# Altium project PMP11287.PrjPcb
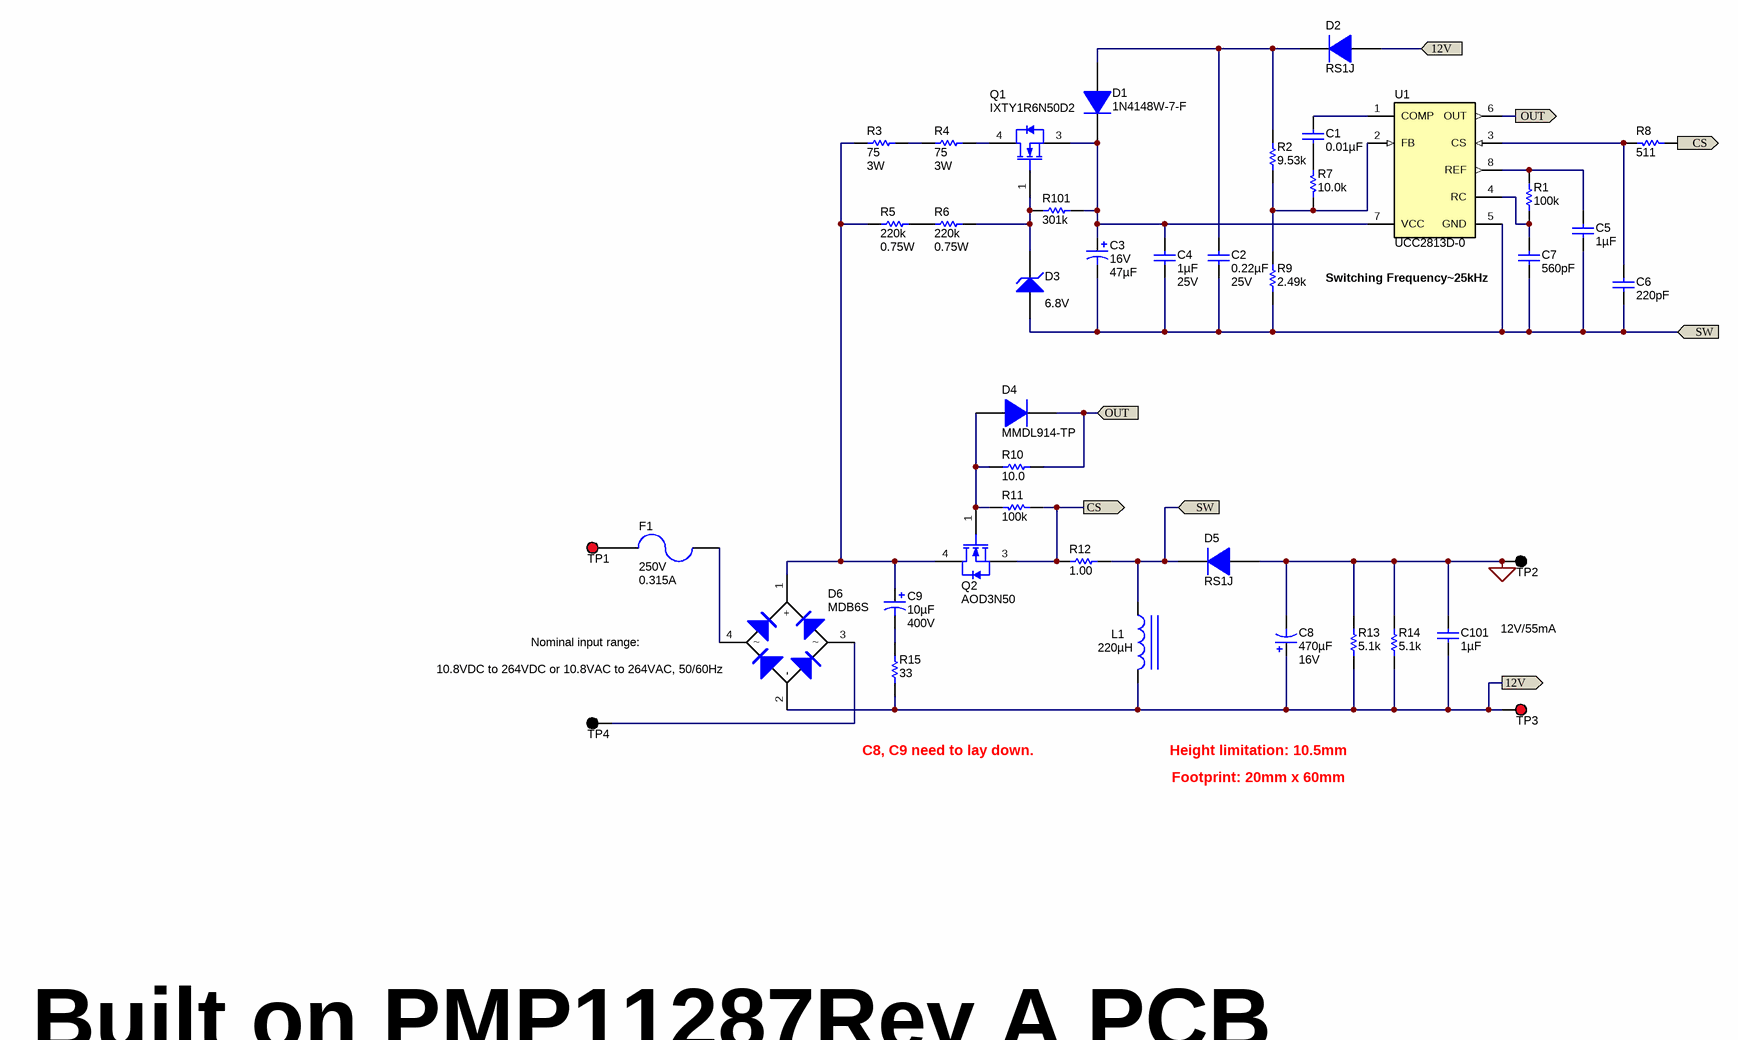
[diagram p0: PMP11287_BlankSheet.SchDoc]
TechSupport: http://www.ti.com/support; SCH_Rev: A; PRJ_Title: Ultra wide input range Buck-Boost converter; PRJ_Number: PMP20182; PRJ_Engineer: Sheng-Yang Yu; PRJ_Customer: Public Release; PCB_Rev: A; PCB_Layout: Sheng-Yang Yu; EVM_Orderable: N/A; CopyrightYear: 2016
1 sheet, 41 parts. Net scope: flat (ports and power ports of the same name join across sheets).
Board file: PMP11287_TID.PcbDoc

## Sheet PMP11287_BlankSheet.SchDoc
size 431 x 279 mm; Date: Not shown in title block; ApprovedBy: Not shown in title block; CheckedBy: Not shown in title block; Author: Not shown in title block; CompanyName: Not shown in title block; Engineer: Not shown in title block; Organization: Not shown in title block; Address1: Not shown in title block; Address2: Not shown in title block; Address3: Not shown in title block; Address4: Not shown in title block; DocumentNumber: 1; Revision: Use project parameter SCH_Rev; SheetNumber: 1; SheetTotal: 1; PageSetup: Record=PageOptions¦CenterHorizontal=True¦CenterVertical=True¦PrintScale=1.00¦XCorrection=1.00¦YCorrection=1.00¦PrintKind=0¦BorderSize=5000000¦LeftOffset=0¦BottomOffset=0¦Orientation=2¦PaperLength=1000¦PaperWidth=1000¦Scale=100¦PaperSource=15¦PrintQuality=600¦MediaType=1¦DitherType=10¦PaperKind=Letter¦PrintScaleMode=1

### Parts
C1  ValueDisplayed: 0.01µF  [0603]  (hidden comment: 06031C103MAT2A)
C2  ValueDisplayed: 0.22µF  Value2: 25V  [0603]  (hidden comment: 06033D224KAT2A)
C3  Value2: 16V  ValueDisplayed: 47µF  [SEPC_C9]  (hidden comment: UVR1C470MDD1TD)
C4  ValueDisplayed: 1µF  Value2: 25V  [1206]  (hidden comment: 12063C105KAT2A)
C5  ValueDisplayed: 1µF  [1206]  (hidden comment: GCM31MR71E105KA37L)
C6  ValueDisplayed: 220pF  [0603]  (hidden comment: GRM1885C1H221JA01D)
C7  ValueDisplayed: 560pF  [0603]  (hidden comment: 06035A561JAT2A)
C8  ValueDisplayed: 470µF  Value2: 16V  [ZL_1000x1600]  (hidden comment: 16YXG470MEFC10X12.5)
C9  ValueDisplayed: 10µF  Value2: 400V  [PW_1000x2000]  (hidden comment: UCS2G100MPD)
C101  ValueDisplayed: 1µF  [0805_HV]  (hidden comment: GRM216R61E105KA12D)
D1  1N4148W-7-F  [SOD-123]
D2  RS1J  [SMA]
D3  value 6.8V  [SOD-123]  (hidden comment: MMSZ5235B-7-F)
D4  MMDL914-TP  [sod-323]
D5  RS1J  [SMA]
D6  MDB6S  [MICRODIP_4]
F1  VAC_V: 250V  Irating_A: 0.315A  [FUSE_372]  (hidden comment: 37203150001)
L1  ValueDisplayed: 220µH  [SDR1006]  (hidden comment: SDR1006-221KL)
Q1  IXTY1R6N50D2  [DPAK]
Q2  AOD3N50  [DPAK]
R1  ValueDisplayed: 100k  [0603]  (hidden comment: CRCW0603100KFKEA)
R2  ValueDisplayed: 9.53k  [0603]  (hidden comment: CRCW06039K53FKEA)
R3  ValueDisplayed: 75  Value2: 3W  [RESAD2032W80L1300D480]  (hidden comment: PNP300JR-73-75R)
R4  ValueDisplayed: 75  Value2: 3W  [RESAD2032W80L1300D480]  (hidden comment: PNP300JR-73-75R)
R5  ValueDisplayed: 220k  Value2: 0.75W  [2010]  (hidden comment: CRCW2010220KJNEF)
R6  ValueDisplayed: 220k  Value2: 0.75W  [2010]  (hidden comment: CRCW2010220KJNEF)
R7  value 10.0k  [0603]  (hidden comment: CRCW060310K0FKEA)
R8  value 511  [0603]  (hidden comment: CRCW0603511RFKEA)
R9  value 2.49k  [0603]  (hidden comment: CRCW06032K49FKEA)
R10  ValueDisplayed: 10.0  [0603]  (hidden comment: CRCW060310R0FKEA)
R11  value 100k  [0603]  (hidden comment: CRCW0603100KFKEA)
R12  ValueDisplayed: 1.00  [1206]  (hidden comment: CRCW12061R00FKEA)
R13  ValueDisplayed: 5.1k  [1206]  (hidden comment: CRCW12065K10JNEA)
R14  ValueDisplayed: 5.1k  [1206]  (hidden comment: CRCW12065K10JNEA)
R15  ValueDisplayed: 33  [2512]  (hidden comment: CRM2512-FX-33R0ELF)
R101  ValueDisplayed: 301k  [1206]  (hidden comment: ERJ-8ENF3013V)
TP1  5000  [Keystone5000]  (value not drawn)
TP2  5001  [Keystone5001]  (value not drawn)
TP3  5000  [Keystone5000]  (value not drawn)
TP4  5001  [Keystone5001]  (value not drawn)
U1  UCC2813D-0  [D0008A_N]

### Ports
12V (in), 12V (out), CS (in), CS (out), OUT (in), OUT (out), SW (in)

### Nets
GND: C8.2(-) C101.1 D5.2(A) R13.2 R14.2 TP2.1
12V: C8.1(+) C101.2 D2.2(A) D6.2(-) L1.2 R13.1 R14.1 R15.1 TP3.1 ; port 12V
CS: Q2.3(S) R8.1 R11.2 R12.1 ; port CS
OUT: D4.1(K) R10.2 U1.6(OUT) ; port OUT
SW: C2.2 C3.2(-) C4.2 C5.2 C6.2 C7.2 D3.2(A) D5.1(K) L1.1 R9.1 R12.2 U1.5(GND) ; port SW
NetC1_1: C1.1 U1.1(COMP)
NetC1_2: C1.2 R7.1
NetC2_1: C2.1 D1.2(A) D2.1(K) R2.2
NetC3_1: C3.1(+) C4.1 D1.1(K) Q1.3(S) R101.2 U1.7(VCC)
NetC5_1: C5.1 R1.2 U1.8(REF)
NetC6_1: C6.1 R8.2 U1.3(CS)
NetC7_1: C7.1 R1.1 U1.4(RC)
NetC9_1: C9.1(+) D6.1(+) Q2.4(D) R3.1 R5.2
NetC9_2: C9.2(-) R15.2
NetD3_1: D3.1(K) Q1.1(G) R6.1 R101.1
NetD4_2: D4.2(A) Q2.1(G) R10.1 R11.1
NetD6_3: D6.3 TP4.1
NetD6_4: D6.4 F1.1
NetF1_2: F1.2 TP1.1
NetQ1_4: Q1.4(D) R4.2
NetR2_1: R2.1 R7.2 R9.2 U1.2(FB)
NetR3_2: R3.2 R4.1
NetR5_1: R5.1 R6.2

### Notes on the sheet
- Switching Frequency|5kHz
- Nominal input range:
- 12V/55mA
- (near D6) 10.8VDC to 264VDC or 10.8VAC to 264VAC, 50/60Hz
- C8, C9 need to lay down.
- Height limitation: 10.5mm
- Footprint: 20mm x 60mm
- Built on PMP11287Rev A PCB

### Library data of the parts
C1 = 06031C103MAT2A: CAP, CERM, 0.01 µF, 100 V, +/- 20%, X7R, 0603; Manufacturer: AVX; Polarized: N; CompType: Capacitor; Value: 0.01uF; U/M: EA; Cap_F: 0.00000001; Tolerance_%: 20; ESR_ohm: 0.098; Value1: 0.098 ohm; VDC_V: 100; Value2: 100V; TaMin_C: -55; TaMax_C: 125
C2 = 06033D224KAT2A: CAP, CERM, 0.22 µF, 25 V, +/- 10%, X5R, 0603; Manufacturer: AVX; Polarized: N; CompType: Capacitor; Value: 0.22uF; U/M: EA; Cap_F: 0.00000022; Tolerance_%: 10; ESR_ohm: 0.036; Value1: 0.036 ohm; VDC_V: 25; TaMin_C: -55; TaMax_C: 85; AEC Category: Q200
C3 = 6SEPC470MW: CAP ALUM 47UF 20% 16V RADIAL; Manufacturer: Nichicon; Polarized: Y; CompType: Capacitor; U/M: EA; Cap_F: 0.00047; Tolerance_%: 20; Value1: 0.007 ohm; VDC_V: 16; ESR_ohm: 0.007; IRMS_A: 5.6; TaMin_C: -55; TaMax_C: 105; Cap_Case: 6.3x9
C4 = 12063C105KAT2A: CAP, CERM, 1uF, 25V, +/-10%, X7R, 1206; Manufacturer: AVX; Polarized: N; CompType: Capacitor; U/M: EA; Cap_F: 0.000001; Tolerance_%: 10; ESR_Ohm: 0.013; Value1: 0.013 ohm; VDC_V: 25; TaMin_C: -55; TaMax_C: 125
C5 = GCM31MR71E105KA37L: CAP, CERM, 1 µF, 25 V, +/- 10%, X7R, AEC-Q200 Grade 1, 1206; Manufacturer: MuRata; Polarized: N; CompType: Capacitor; Value: 1uF; U/M: EA; Cap_F: 0.000001; Tolerance_%: 10; Value1: Unknown; VDC_V: 25; Value2: 25V; TaMin_C: -55; TaMax_C: 125; AEC Category: Q200; AEC Qualified: Y; AEC Grade: 1
C6 = GRM1885C1H221JA01D: CAP, CERM, 220 pF, 50 V, +/- 5%, C0G/NP0, 0603; Manufacturer: MuRata; Polarized: N; CompType: Capacitor; Value: 220pF; U/M: EA; Cap_F: 0.00000000022; Tolerance_%: 5; Value1: Unknown; VDC_V: 50; Value2: 50V; TaMin_C: -55; TaMax_C: 125; AEC Category: Q200
C7 = 06035A561JAT2A: CAP, CERM, 560 pF, 50 V, +/- 5%, C0G/NP0, 0603; Manufacturer: AVX; Polarized: N; CompType: Capacitor; Value: 560pF; U/M: EA; Cap_F: 0.00000000056; Tolerance_%: 5; ESR_ohm: 0.059; Value1: 0.059 ohm; VDC_V: 50; Value2: 50V; TaMin_C: -55; TaMax_C: 125; AEC Category: Q200
C8 = 63ZL120MEFC10X16: CAP ALUM 470UF 20% 16V RADIAL; Manufacturer: Rubycon; Polarized: Y; CompType: Capacitor; U/M: EA; Cap_F: 0.00012; Tolerance_%: 20; Value1: 0.945 ohm; VDC_V: 16; ESR_ohm: 0.945; IRMS_A: 0.12; TaMin_C: -40; TaMax_C: 105; Cap_Case: 10x16; AEC Category: Q200; AEC Qualified: N
C9 = UPW2D220MPD: CAP ALUM 10UF 20% 400V RADIAL; Manufacturer: Nichicon; Polarized: Y; CompType: Capacitor; U/M: EA; Cap_F: 0.000022; Tolerance_%: 20; Value1: Unknown; VDC_V: 400; IRMS_A: 0.14; TaMin_C: -40; TaMax_C: 105; Cap_Case: 10x20; AEC Category: Q200
C101 = GRM216R61E105KA12D: CAP, CERM, 1 µF, 25 V, +/- 10%, X5R, 0805; Manufacturer: MuRata; Polarized: N; CompType: Capacitor; Value: 1uF; U/M: EA; Cap_F: 0.000001; Tolerance_%: 10; ESR_ohm: 0.009; Value1: 0.009 ohm; VDC_V: 25; Value2: 25V; TaMin_C: -55; TaMax_C: 85; Cap_Case: 0805; AEC Category: Q200
D1 = 1N4148W-7-F: Diode, Ultrafast, 100V, 0.15A, SOD-123; Manufacturer: Diodes Inc.; U/M: EA; Vf_V: 1.25; Value2: 1.25V; Io_A: 0.15; Vr_V: 100; TJmax_C: 150
D2 D5 = RS1G-13-F: DIODE GEN PURP 600V 1A SMA; Manufacturer: Fairchild Semiconductor; U/M: EA; Vf_V: 1.3; Value2: 1.3V; Io_A: 1; Vr_V: 400; TJmax_C: 150; RJC_CperW: 20; Type: Ultrafast; AEC Category: Q101
D3 = MMSZ5235B-7-F: Diode, Zener, 6.8 V, 500 mW, SOD-123; Manufacturer: Diodes Inc.; SymbolCreator: a0412235; U/M: EA; Power_W: 0.5; Vz_V: 6.8; Value1: 0.5W; RJA_CperW: 350; AEC Category: Q101
D4 = MMDL914-TP: Diode, Switching, 100V, 0.2A, SOD-323; Manufacturer: Micro Commercial Components; U/M: EA; Vf_V: 1; Value2: 1V; Io_A: 0.2; Vr_V: 100; TJmax_C: 150; RJC_CperW: 635
D6 = MDB6S: Diode, Switching-Bridge, 600 V, 1 A, MICRODIP_4; Manufacturer: Fairchild Semiconductor; U/M: EA; Vf_V: 1.1; Value: 600V; Value1: 1A; Value2: 1.1V; Io_A: 1; Vr_V: 600; TJmax_C: 150; AEC Category: Q101
F1 = 37203150001: Fuse, 0.315 A, 250VAC/VDC, TH; Manufacturer: Littelfuse; VDC_V: 250
L1 = SDR1006-221KL: Inductor, Drum Core, Ferrite, 220 µH, 0.66 A, 0.73 ohm, SMD; Manufacturer: Bourns; Value: 220uH; Ind_H: 220.0E-6; Imax_A: 0.66; Irms: 0.66A @ 40C rise; Isat: 1.19A @ 10% inductance drop; DCR_ohm: 0.73; Value2: 0.66A; AEC Category: Q200
Q1 = AOD3N50: MOSFET N-CH 500V 1.6A DPAK; Manufacturer: IXYS; Alternate Manufacturer: None; U/M: EA; ChType: N; VdsMax_V: 500; Value1: ? ohm; Value2: 6.7 nC; QgTyp_nC: 6.7; Vgs_V: 30; IdsMax_A: 2.8; AEC Category: Q101
Q2 = AOD3N50: MOSFET, N-CH, 500 V, 2.8 A, DPAK; Manufacturer: AOS; Alternate Manufacturer: None; U/M: EA; ChType: N; Value: 500V; VdsMax_V: 500; Value1: ? ohm; Value2: 6.7 nC; QgTyp_nC: 6.7; Vgs_V: 30; IdsMax_A: 2.8; AEC Category: Q101
R1 = CRCW0603100KFKEA: RES, 100 k, 1%, 0.1 W, 0603; Manufacturer: Vishay-Dale; CompType: Resistor; Value: 100k; Res_ohm: 100000; Tolerance_%: 1; Power_W: 0.1; Value2: 0.1W; VDC_V: 75; TempCo: 100 ppm/C; EIA_Code: E96; U/M: EA
R2 = CRCW06039K53FKEA: RES, 9.53 k, 1%, 0.1 W, 0603; Manufacturer: Vishay-Dale; CompType: Resistor; Value: 9.53k; Res_ohm: 9530; Value_Code: 9k53; Tolerance_%: 1; Power_W: 0.1; Value2: 0.1W; VDC_V: 75; TempCo: 100 ppm/C; EIA_Code: E96; U/M: EA
R3 R4 = AC03000001009JAC00: RES 75 OHM 3W 5% AXIAL; Manufacturer: Yageo; CompType: Resistor; Value: 75; Res_ohm: 10; Value_Code: 75R0; Tolerance_%: 5; Power_W: 3; TempCo: 80 ppm/C; EIA_Code: E24; U/M: EA
R5 R6 = CRCW2010220KJNEF: RES, 220 k, 5%, 0.75 W, 2010; Manufacturer: Vishay-Dale; CompType: Resistor; Value: 220k; Res_ohm: 220000; Tolerance_%: 5; Power_W: 0.75; VDC_V: 400; TempCo: 200 ppm/C; EIA_Code: E24; U/M: EA; AEC Category: Q200
R7 = CRCW060310K0FKEA: RES, 10.0k ohm, 1%, 0.1W, 0603; Manufacturer: Vishay-Dale; CompType: Resistor; Res_ohm: 10000; Value_Code: 10k0; Tolerance_%: 1; Power_W: 0.1; VDC_V: 75; TempCo: 100 ppm/C; EIA_Code: E96; U/M: EA
R8 = CRCW0603511RFKEA: RES, 511 ohm, 1%, 0.1W, 0603; Manufacturer: Vishay-Dale; CompType: Resistor; Value_Code: 511R; Tolerance_%: 1; Power_W: 0.1; VDC_V: 75; TempCo: 100 ppm/C; EIA_Code: E96; U/M: EA
R9 = CRCW06032K49FKEA: RES, 2.49k ohm, 1%, 0.1W, 0603; Manufacturer: Vishay-Dale; CompType: Resistor; Res_ohm: 2490; Value_Code: 2k49; Tolerance_%: 1; Power_W: 0.1; VDC_V: 75; TempCo: 100 ppm/C; EIA_Code: E96; U/M: EA
R10 = CRCW060310R0FKEA: RES, 10.0, 1%, 0.1 W, 0603; Manufacturer: Vishay-Dale; CompType: Resistor; Value: 10.0; Res_ohm: 10; Value_Code: 10R0; Tolerance_%: 1; Power_W: 0.1; Value2: 0.1W; VDC_V: 75; TempCo: 100 ppm/C; EIA_Code: E96; U/M: EA; AEC Category: Q200
R11 = CRCW0603100KFKEA: RES, 100k ohm, 1%, 0.1W, 0603; Manufacturer: Vishay-Dale; CompType: Resistor; Res_ohm: 100000; Tolerance_%: 1; Power_W: 0.1; VDC_V: 75; TempCo: 100 ppm/C; EIA_Code: E96; U/M: EA
R12 = CRCW12061R00FKEA: RES, 1.00, 1%, 0.25 W, 1206; Manufacturer: Vishay-Dale; CompType: Resistor; Value: 1.00; Res_ohm: 1; Value_Code: 1R00; Power_W: 0.25; Value2: 0.25W; VDC_V: 200; TempCo: 100 ppm/C; EIA_Code: E96; U/M: EA; AEC Category: Q200
R13 R14 = CRCW12065K10JNEA: RES, 5.1 k, 5%, 0.25 W, 1206; Manufacturer: Vishay-Dale; CompType: Resistor; Value: 5.1k; Res_ohm: 5100; Value_Code: 5k10; Tolerance_%: 5; Power_W: 0.25; Value2: 0.25W; VDC_V: 200; TempCo: 200 ppm/C; EIA_Code: E24; U/M: EA
R15 = CRCW251233R2FKEG: RES SMD 33 OHM 1% 2W 2512; Manufacturer: Bourns Inc.; CompType: Resistor; Value: 33.2; Tolerance_%: 1; Value2: 1W; VDC_V: 500; TempCo: 100 ppm/C; EIA_Code: E96; U/M: EA; AEC Category: Q200; AEC Qualified: Y; AEC Grade: 0
R101 = ERJ-8ENF3013V: RES, 301 k, 1%, 0.25 W, 1206; Manufacturer: Panasonic; CompType: Resistor; Value: 301k; Res_ohm: 301000; Tolerance_%: 1; Power_W: 0.25; Value2: 0.25W; VDC_V: 200; TempCo: 100 ppm/C; EIA_Code: E96; U/M: EA; AEC Category: Q200
TP1 TP3 = 5000: Test Point, Miniature, Red, TH; Manufacturer: Keystone; CompType: Test Point Loop; U/M: EA
TP2 TP4 = 5001: Test Point, Miniature, Black, TH; Manufacturer: Keystone; CompType: Test Point Loop; U/M: EA
U1 = UCC2813QDR-3Q1: IC REG CTRLR BST FLYBK PWM 8SOIC; Manufacturer: Texas Instruments; Alternate PartNumber: Equivalent; Control Method: Current; Duty Cycle(Max)(%): 100; Eco-Plan: Green (RoHS & no Sb/Br); Frequency(Max)(kHz): 1000; Regulated Outputs(#): 1; SubFamily: PWM Controller; Topology: Boost, Flyback, Forward

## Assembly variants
001: not fitted FID1 FID2 FID3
